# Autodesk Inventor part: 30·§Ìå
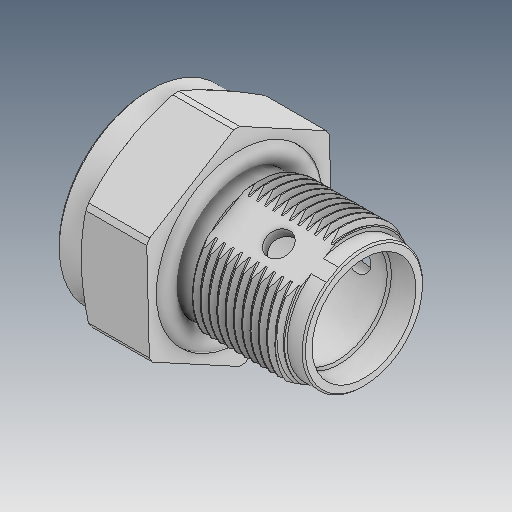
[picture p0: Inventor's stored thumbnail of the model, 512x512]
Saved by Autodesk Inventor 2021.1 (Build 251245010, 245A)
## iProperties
Created: 2019-05
Part Number: 30·§Ìå
Material: Ogólny
Document SubType Name: Modeling
Designer: user
Density: 1 g/cm^3
Appearance: Domyślna
Author: user
Revision Number: ÈÎºÎ
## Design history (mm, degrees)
feature "ÊäÈë1"
feature "ÊäÈë2"
node "Bryła1"
node "Bryła2"
